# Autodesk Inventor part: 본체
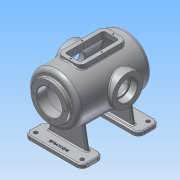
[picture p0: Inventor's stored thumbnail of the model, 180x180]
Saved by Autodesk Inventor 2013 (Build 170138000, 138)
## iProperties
Created: 2016-02
Part Number: 본체
Material: 알루미늄 6061
Document SubType Name: Modeling
Designer: mduedu
Density: 2.71 g/cm^3
Mass: 3305.57 g
Surface Area: 2487 cm^2
Volume: 1219.77 cm^3
Author: mduedu
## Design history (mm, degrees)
sketch "스케치2"
  geometry: L1 (0, 100)-(0, -100); L2 (65, -87.083)-(65, 100); L3 (65, 100)-(0, 100); A1 r 170 centre (0, 70) between (0, -100) and (65, -87.083); 2 further points
  constraints: 6 end point, 2 point on circle, 1 centre point, 1 coincident, 1 horizontal, 1 midpoint, 1 parallel, 1 point on line, 1 vertical
  dimensions: "d3" = 200 distance of L1.start L1.end; "d5" = 130 diameter of L2 L1; "d6" = 170 radius of A1
revolve "회전1" sketch "스케치2" stored, may be unused: angle "d7" = 90 deg
sketch "스케치3"
  geometry: C1 r 47.5 at (0, 0); 1 further point
  constraints: 1 centre point, 1 coincident
  dimensions: "d8" = 95 diameter of C1
extrude "돌출2" join sketch "스케치3" distance "d10" = 10; taper "d11" = 0 deg
sketch "스케치5"
  geometry: L1 (47.5, 110)-(47.5, 100) reference; L2 (47.5, 100)-(65, 100) reference; L3 (65, 100)-(65, -87.083) reference; L4 (-65, -87.083)-(-65, 100) reference; L5 (-65, 100)-(-47.5, 100) reference; L6 (-47.5, 100)-(-47.5, 110) reference; L7 (-47.5, 110)-(47.5, 110) reference; L8 (55, 85)-(55, -80.25); L9 (0, 85)-(55, 85); L10 (0, 85)-(0, -90); A1 r 170 centre (0, 70) between (-65, -87.083) and (0, -100) reference; A2 r 170 centre (0, 70) between (0, -100) and (65, -87.083) reference; A3 r 160 centre (0, 70) between (0, -90) and (55, -80.25); 1 further point
  constraints: 6 end point, 2 point on circle, 1 centre point, 1 parallel, 1 perpendicular, 1 point on line, 1 vertical
  dimensions: "d13" = 10 distance between parallel lines of L3 L8; "d14" = 10 radial gap between concentric circles of A3 A1; "d15" = 15 distance between parallel lines of L9 L2
revolve "회전2" sketch "스케치5" stored, may be unused: angle "d16" = 90 deg
hole "구멍1" diameter "d19" = 65; stored, may be unused: countersink angle "d23" = 90 deg, drill point angle "d25" = 118 deg; dims "d17" = 10, "d18" = 10, "d20" = 6, "d21" = 4, "d22" = 2, "d24" = 8
node "작업 평면1"
sketch "스케치6"
  geometry: L1 (47.5, 110)-(-47.5, 110) reference; C1 r 40 at (0, -17); 1 further point
  constraints: 1 centre point, 1 vertical alignment
  dimensions: "d27" = 80 diameter of C1; "d29" = 127 distance from line of C1.centre L1
extrude "돌출3" join sketch "스케치6" stored distance "d30" = 10; taper "d31" = 0 deg
hole "구멍2" diameter "d34" = 42; stored, may be unused: countersink angle "d38" = 90 deg, drill point angle "d40" = 118 deg; dims "d32" = 10, "d33" = 10, "d35" = 6, "d36" = 52, "d37" = 18, "d39" = 8
sketch "스케치7" dims "d41" = 65
  geometry: C1 r 40 at (0, 0) reference; 3 further points
  constraints: 2 vertical alignment, 1 coincident, 2 other
hole "구멍3" sketch "스케치7" at (0, 32.5) diameter "d43" = 3.242; stored, may be unused: countersink angle "d47" = 90 deg, drill point angle "d49" = 118 deg; dims "d44" = 11, "d45" = 13, "d46" = 18, "d48" = 13
sketch "스케치8" dims "d53" = 80
  geometry: 3 further points
  constraints: 2 vertical alignment, 1 coincident, 2 other
hole "구멍4" sketch "스케치8" at (0, 40) diameter "d56" = 3.242; stored, may be unused: countersink angle "d60" = 90 deg, drill point angle "d62" = 118 deg; dims "d57" = 11, "d58" = 13, "d59" = 18, "d61" = 13
fillet "모깎기1" dims "d66" = 10
fillet "모깎기2" dims "d67" = 3
fillet "모깎기3" dims "d68" = 0.3
chamfer "모따기1" distance "d69" = 1; stored, may be unused: second distance "d70" = 2, angle "d71" = 45 deg
node "작업 평면2"
sketch "스케치9"
  geometry: L1 (75, 100)-(-75, 100); L2 (-75, 100)-(-75, -100); L3 (-75, -100)-(75, -100); L4 (75, -100)-(75, 100); 1 further point
  constraints: 8 end point, 2 parallel, 1 horizontal, 1 perpendicular
  dimensions: "d73" = 200 distance of L3.end L1.start; "d75" = 150 distance of L2.end L3.end; "d76" = 100 distance from line of L1 point (0, 0); "d77" = 75 distance from line of L4 point (0, 0)
extrude "돌출4" join sketch "스케치9" distance "d78" = 10; taper "d79" = 0 deg
sketch "스케치10"
  geometry: L1 (-75, -100)-(75, -100) reference; L2 (75, 100)-(-75, 100) reference; L3 (0, -100)-(0, 100); L4 (-75, 100)-(-75, -100) reference; L5 (75, -100)-(75, 100) reference; L6 (-75, 0)-(75, 0); L7 (-50, -63)-(50, -63); L8 (50, -63)-(50, -55); L9 (50, -55)-(-50, -55); L10 (-50, -55)-(-50, -63); L11 (-50, 63)-(50, 63); L12 (50, 63)-(50, 55); L13 (50, 55)-(-50, 55); L14 (-50, 55)-(-50, 63); 1 further point
  constraints: 20 end point, 4 midpoint, 4 symmetric about line, 2 parallel, 1 horizontal, 1 perpendicular, 1 other
  dimensions: "d80" = 8 distance of L9.end L7.start; "d82" = 100 distance of L7.start L7.end; "d83" = 55 distance between parallel lines of L9 L6
extrude "돌출5" join sketch "스케치10" stored distance "d84" = 10; taper "d85" = 0 deg
feature "면 기울기1" dims angle "d86" = 10 deg
sketch "스케치11"
  geometry: L1 (-110, 55)-(-51.482, 55) reference; L2 (-110, -55)-(-51.482, -55) reference; L3 (-95, 55)-(-95, -55); L4 (-65, 90)-(-65, -80.25) reference; 1 further point
  constraints: 2 end point, 2 point on line, 1 perpendicular
  dimensions: "d87" = 30 distance between parallel lines of L3 L4
feature "리브1" sketch "스케치11" dims "d88" = 1, "d89" = 8, "d90" = 0, "d91" = 0, "d92" = 1, "d93" = 1
sketch "스케치12"
  geometry: L1 (-110, 55)-(-51.482, 55) reference; L2 (-110, -55)-(-51.482, -55) reference; L3 (-110, 100)-(-110, -100) reference; L4 (-120, 152)-(-120, -142) reference; L5 (-110, 45)-(-120, 45); L6 (-120, 45)-(-120, -45); L7 (-120, -45)-(-110, -45); L8 (-110, -45)-(-110, 45); 1 further point
  constraints: 8 end point, 2 parallel, 2 point on line, 1 horizontal, 1 perpendicular
  dimensions: "d94" = 10 distance between parallel lines of L7 L2; "d95" = 10 distance between parallel lines of L1 L5
extrude "돌출6" cut sketch "스케치12" stored distance "d96" = 10; taper "d97" = 0 deg
fillet "모깎기4" dims "d98" = 15
sketch "스케치13"
  geometry: C1 r 5 at (-60, -85); C2 r 5 at (60, -85); C3 r 5 at (60, 85); C4 r 5 at (-60, 85); A1 r 15 centre (-60, -85) between (-75, -85) and (-60, -100) reference; A2 r 15 centre (60, -85) between (60, -100) and (75, -85) reference; A3 r 15 centre (60, 85) between (75, 85) and (60, 100) reference; A4 r 15 centre (-60, 85) between (-60, 100) and (-75, 85) reference; 1 further point
  constraints: 4 centre point, 4 coincident, 3 equal radius
  dimensions: "d99" = 10 diameter of C1
extrude "돌출7" cut sketch "스케치13" stored distance "d101" = 10; taper "d102" = 0 deg
fillet "모깎기5" dims "d103" = 3, "d104" = 3
fillet "모깎기6" dims "d105" = 3
sketch "스케치14"
  geometry: L1 (-60, -100)-(60, -100) reference; 2 further points
  constraints: 1 vertical alignment, 1 other
  dimensions: "d106" = 15 distance from line of point (0, -85) L1
feature "엠보싱1" sketch "스케치14" dims "d3" = 200, "d5" = 130, "d6" = 170, "d14" = 10, "d107" = 0.5, "d108" = 0
node "작업 평면3"
sketch "스케치15"
  geometry: L1 (-30, 60)-(30, 60); L2 (30, 60)-(30, -60); L3 (30, -60)-(-30, -60); L4 (-30, -60)-(-30, 60); 2 further points
  constraints: 8 end point, 2 parallel, 1 horizontal, 1 midpoint, 1 perpendicular, 1 vertical alignment
  dimensions: "d110" = 60 distance of L2.end L3.end; "d112" = 60 distance from line of L3 point (0, 0); "d113" = 120 distance of L1.end L2.end
extrude "돌출8" join sketch "스케치15" stored distance "d114" = 10; taper "d115" = 0 deg
fillet "모깎기7" dims "d116" = 15
sketch "스케치16"
  geometry: L1 (-30, -45)-(-30, 45) reference; L2 (-15, 60)-(15, 60) reference; L3 (30, 45)-(30, -45) reference; L4 (15, -60)-(-15, -60) reference; L5 (15, 50)-(-15, 50); L6 (-20, 45)-(-20, -45); L7 (-15, -50)-(15, -50); L8 (20, -45)-(20, 45); A1 r 15 centre (-15, -45) between (-30, -45) and (-15, -60) reference; A2 r 15 centre (-15, 45) between (-15, 60) and (-30, 45) reference; A3 r 15 centre (15, 45) between (30, 45) and (15, 60) reference; A4 r 15 centre (15, -45) between (15, -60) and (30, -45) reference; A5 r 5 centre (-15, 45) between (-15, 50) and (-20, 45); A6 r 5 centre (-15, -45) between (-20, -45) and (-15, -50); A7 r 5 centre (15, -45) between (15, -50) and (20, -45); A8 r 5 centre (15, 45) between (20, 45) and (15, 50); 1 further point
  constraints: 8 end point, 8 point on circle, 4 centre point, 7 other
  dimensions: "d117" = 10 distance between parallel lines of L6 L1
extrude "돌출9" cut sketch "스케치16" stored distance "d118" = 10; taper "d119" = 0 deg
fillet "모깎기8" dims "d120" = 3
sketch "스케치17"
  geometry: L1 (-30, -45)-(-30, 45) reference; L2 (-15, 60)-(15, 60) reference; L3 (30, 45)-(30, -45) reference; L4 (15, -60)-(-15, -60) reference; L5 (20, -45)-(20, 45) reference; L6 (15, 50)-(-15, 50) reference; L7 (-20, 45)-(-20, -45) reference; L8 (-15, -50)-(15, -50) reference; L9 (15, 55)-(-15, 55); L10 (-25, 45)-(-25, -45); L11 (-15, -55)-(15, -55); L12 (25, -45)-(25, 45); A1 r 15 centre (-15, 45) between (-15, 60) and (-30, 45) reference; A2 r 15 centre (15, 45) between (30, 45) and (15, 60) reference; A3 r 15 centre (15, -45) between (15, -60) and (30, -45) reference; A4 r 15 centre (-15, -45) between (-30, -45) and (-15, -60) reference; A5 r 5 centre (15, -45) between (15, -50) and (20, -45) reference; A6 r 5 centre (15, 45) between (20, 45) and (15, 50) reference; A7 r 5 centre (-15, 45) between (-15, 50) and (-20, 45) reference; A8 r 5 centre (-15, -45) between (-20, -45) and (-15, -50) reference; A9 r 10 centre (-15, 45) between (-15, 55) and (-25, 45); A10 r 10 centre (-15, -45) between (-25, -45) and (-15, -55); A11 r 10 centre (15, -45) between (15, -55) and (25, -45); A12 r 10 centre (15, 45) between (25, 45) and (15, 55); 5 further points
  constraints: 8 end point, 8 point on circle, 4 centre point, 4 midpoint, 7 other
  dimensions: "d121" = 5 distance between parallel lines of L10 L1
hole "구멍5" sketch "스케치17" at (0, 55), (25, 0), (0, -55), (-25, 0) diameter "d122" = 3.242; stored, may be unused: countersink angle "d126" = 90 deg, drill point angle "d128" = 118 deg; dims "d123" = 9, "d124" = 13, "d125" = 18, "d127" = 11
fillet "모깎기9" dims "d129" = 3
node "솔리드2"
pattern_circular "원형 패턴1" dims angle "d51" = 360 deg
mirror "대칭1"
pattern_circular "원형 패턴2" dims angle "d64" = 360 deg
node "절단 모서리 투영1"
node "절단 모서리 투영2"
node "절단 모서리 투영3"
other parameters: "d26" = 75
